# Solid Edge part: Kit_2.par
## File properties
Username: bmolnar
Dokumentum tartalom típus: 0
Author: bmolnar
Last saved by: bmolnar
Revision: 77
Sűrűség: 0,000 kg/m^3
Pontosság: 0,990
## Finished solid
Body 1: solid body, 23 faces, 39 edges, 29 vertices.
  Faces by surface: plane 11, cylinder 8, cone 3, torus 1
  Edges by curve: circle 21, line 18
Bounding box of the edges (mm; curved faces can reach further): 35.700 x 35.450 x 3.850, from (-17.85, -16.85, 0.6) to (17.85, 18.6, 4.45).
Cylindrical faces by radius (mm): R1.25 x2, R2.25 x2, R11.5 x1, R15.9 x1, R16.85 x1, R17.85 x1
Conical faces (half-angle, radius in mm at the cone's reference point): 45 deg R11.25 x1, 45 deg R16.75 x2
Toroidal faces (ring radius, tube radius in mm): R11.9 r0.4 x1
Planar faces by outward normal: +z 2, -z 5, oblique 4
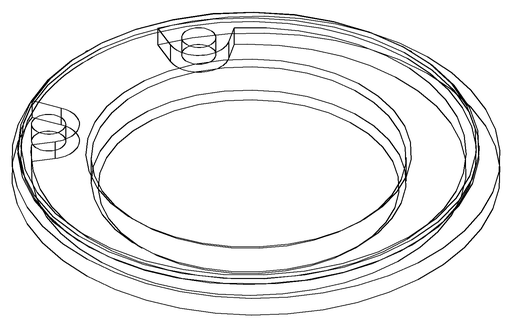
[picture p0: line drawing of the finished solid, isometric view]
